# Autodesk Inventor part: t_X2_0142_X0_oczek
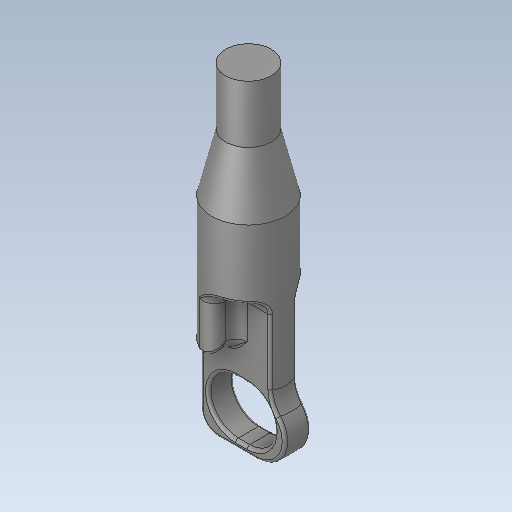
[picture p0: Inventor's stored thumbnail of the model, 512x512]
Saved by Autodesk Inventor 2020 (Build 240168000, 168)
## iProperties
Created: 2015-11
Part Number: t_X2_0142_X0_oczek
Material: Ogólny
Document SubType Name: Modeling
Designer: Tomasz
Density: 1 g/cm^3
Appearance: Domyślna
Sending System: SolidWorks 2017
Last Author: Tomasz
Last Saved: 2017-11-19
Author: Tomasz
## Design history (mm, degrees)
feature "Imported1"
node "Bryła1"
